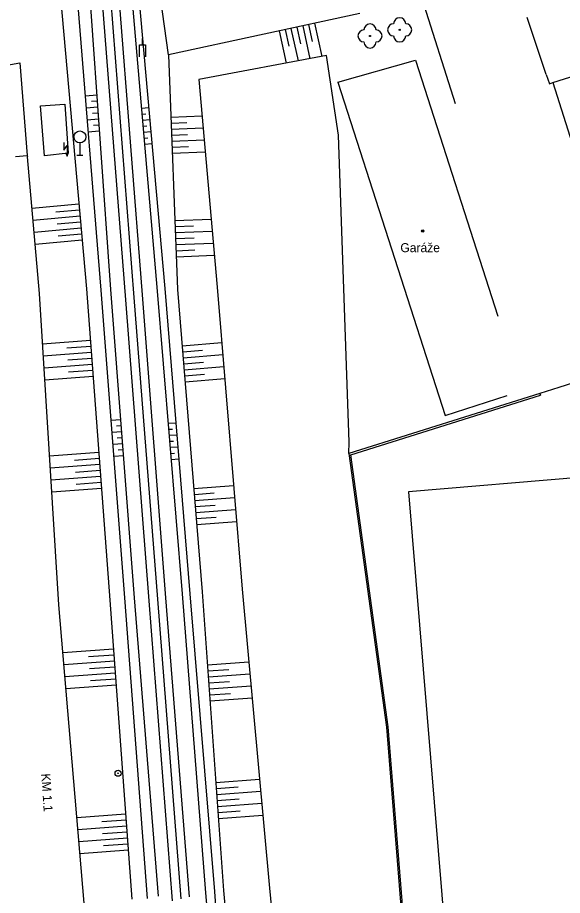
# Model space of a CAD drawing. Extents: x -539244 to -537359, y -1183785 to -1181851.
# Drawn here: x -537718.9 to -537673.7, y -1182189.8 to -1182116.9 of the extents above; entities that cross this region are included whole.
import ezdxf

# ---------------------------------------------------------------- set-up
doc = ezdxf.new("R2010")
doc.units = 0
for name, color, linetype in [('Vrstva 10', 7, 'Continuous'), ('Vrstva 12', 7, 'Continuous'), ('Vrstva 13', 7, 'Continuous'), ('Vrstva 14', 7, 'Continuous'), ('Vrstva 15', 7, 'Continuous'), ('Vrstva 22', 7, 'Continuous'), ('Vrstva 24', 7, 'Continuous'), ('Vrstva 38', 7, 'Continuous'), ('Vrstva 39', 7, 'Continuous'), ('Vrstva 41', 7, 'Continuous'), ('Vrstva 5', 7, 'Continuous'), ('Vrstva 7', 7, 'Continuous'), ('Vrstva 8', 7, 'Continuous')]:
    doc.layers.add(name, color=color, linetype=linetype)

msp = doc.modelspace()

# ---------------------------------------------------------------- linework, layer by layer
at = {"layer": 'Vrstva 10'}
msp.add_line((-537689.19, -1182103.13), (-537682.58, -1182124.019), dxfattribs=at)
at = {"layer": 'Vrstva 12'}
for p, q in [((-537711.952, -1182114.759), (-537709.968, -1182140.329)), ((-537708.55, -1182139.921), (-537710.51, -1182114.75)), ((-537713.75, -1182127.309), (-537713.75, -1182128.309)), ((-537714, -1182128.309), (-537713.5, -1182128.309)), ((-537709.968, -1182140.329), (-537708.028, -1182165.312)), ((-537706.602, -1182165.047), (-537708.55, -1182139.921)), ((-537704.656, -1182189.88), (-537706.602, -1182165.047)), ((-537708.028, -1182165.312), (-537706.086, -1182190.197))]:
    msp.add_line(p, q, dxfattribs=at)
for centre, radius in [((-537713.75, -1182126.809), 0.5), ((-537710.58, -1182179.624), 0.25), ((-537710.58, -1182179.624), 0.03)]:
    msp.add_circle(centre, radius, dxfattribs=at)
at = {"layer": 'Vrstva 13'}
for p, q in [((-537711.23, -1182114.755), (-537709.258, -1182140.125)), ((-537709.258, -1182140.125), (-537707.316, -1182165.18)), ((-537707.316, -1182165.18), (-537705.372, -1182190.039))]:
    msp.add_line(p, q, dxfattribs=at)
at = {"layer": 'Vrstva 14'}
for p, q in [((-537706.396, -1182120.004), (-537707.724, -1182110.357)), ((-537707.33, -1182139.284), (-537709.748, -1182111.262)), ((-537709.198, -1182111.395), (-537706.702, -1182139.384)), ((-537711.174, -1182139.479), (-537713.11, -1182112.226)), ((-537714.084, -1182114.029), (-537712.014, -1182139.53)), ((-537715.384, -1182115.108), (-537713.198, -1182139.404)), ((-537690.5, -1182116.556), (-537706.396, -1182120.004)), ((-537706.396, -1182120.004), (-537705.632, -1182139.457)), ((-537733.226, -1182123.066), (-537718.732, -1182120.669)), ((-537713.198, -1182139.404), (-537711.262, -1182165.246)), ((-537712.014, -1182139.53), (-537710.046, -1182165.064)), ((-537709.2, -1182165.065), (-537711.174, -1182139.479)), ((-537705.238, -1182164.741), (-537707.33, -1182139.284)), ((-537706.702, -1182139.384), (-537704.61, -1182164.735)), ((-537705.632, -1182139.457), (-537703.582, -1182164.572)), ((-537703.582, -1182164.572), (-537701.808, -1182189.341)), ((-537711.262, -1182165.246), (-537709.424, -1182190.062)), ((-537710.046, -1182165.064), (-537708.156, -1182190.022)), ((-537707.232, -1182189.835), (-537709.2, -1182165.065)), ((-537703.274, -1182189.536), (-537705.238, -1182164.741)), ((-537704.61, -1182164.735), (-537702.578, -1182189.421)), ((-537701.808, -1182189.341), (-537699.502, -1182214.94)), ((-537701.302, -1182215.217), (-537703.274, -1182189.536)), ((-537702.578, -1182189.421), (-537700.582, -1182215.071))]:
    msp.add_line(p, q, dxfattribs=at)
msp.add_lwpolyline([(-537718.732, -1182120.669), (-537718.118, -1182128.34), (-537718.108, -1182128.458)], dxfattribs=at)
at = {"layer": 'Vrstva 15'}
for p, q in [((-537696.702, -1182117.901), (-537696.404, -1182119.276)), ((-537696.214, -1182117.795), (-537695.627, -1182120.5)), ((-537695.726, -1182117.689), (-537695.424, -1182119.081)), ((-537695.236, -1182117.583), (-537694.645, -1182120.316)), ((-537694.748, -1182117.477), (-537694.442, -1182118.887)), ((-537694.26, -1182117.371), (-537693.66, -1182120.131)), ((-537697.192, -1182118.007), (-537696.61, -1182120.684)), ((-537712.32, -1182123.341), (-537713.322, -1182123.412)), ((-537712.25, -1182124.338), (-537713.24, -1182124.409)), ((-537712.286, -1182123.839), (-537712.784, -1182123.875)), ((-537708.614, -1182124.416), (-537708.04, -1182124.366)), ((-537712.214, -1182124.837), (-537712.708, -1182124.872)), ((-537708.57, -1182124.914), (-537708.284, -1182124.889)), ((-537706.194, -1182125.152), (-537703.604, -1182125.051)), ((-537712.18, -1182125.336), (-537713.16, -1182125.405)), ((-537712.144, -1182125.834), (-537712.632, -1182125.869)), ((-537708.528, -1182125.412), (-537707.952, -1182125.362)), ((-537708.484, -1182125.91), (-537708.196, -1182125.885)), ((-537706.174, -1182125.652), (-537704.868, -1182125.601)), ((-537712.108, -1182126.333), (-537713.078, -1182126.402)), ((-537708.442, -1182126.408), (-537707.864, -1182126.358)), ((-537706.154, -1182126.152), (-537703.516, -1182126.048)), ((-537706.134, -1182126.651), (-537704.804, -1182126.599)), ((-537708.398, -1182126.906), (-537708.108, -1182126.881)), ((-537708.356, -1182127.405), (-537707.774, -1182127.354)), ((-537706.116, -1182127.151), (-537703.428, -1182127.045)), ((-537706.096, -1182127.65), (-537704.74, -1182127.597)), ((-537706.076, -1182128.15), (-537703.34, -1182128.043)), ((-537713.83, -1182132.384), (-537717.734, -1182132.735)), ((-537713.784, -1182132.882), (-537715.738, -1182133.057)), ((-537713.74, -1182133.38), (-537717.646, -1182133.731)), ((-537713.694, -1182133.878), (-537715.648, -1182134.053)), ((-537705.856, -1182133.749), (-537702.846, -1182133.63)), ((-537713.65, -1182134.376), (-537717.56, -1182134.727)), ((-537705.836, -1182134.248), (-537704.32, -1182134.189)), ((-537705.818, -1182134.748), (-537702.758, -1182134.628)), ((-537713.56, -1182135.372), (-537717.472, -1182135.724)), ((-537713.606, -1182134.874), (-537715.56, -1182135.05)), ((-537705.798, -1182135.247), (-537704.256, -1182135.187)), ((-537705.778, -1182135.747), (-537702.67, -1182135.625)), ((-537705.758, -1182136.247), (-537704.192, -1182136.185)), ((-537705.738, -1182136.746), (-537702.582, -1182136.622)), ((-537712.876, -1182143.698), (-537716.854, -1182143.996)), ((-537705.25, -1182144.144), (-537701.966, -1182143.876)), ((-537712.802, -1182144.695), (-537716.792, -1182144.994)), ((-537712.838, -1182144.197), (-537714.83, -1182144.346)), ((-537705.208, -1182144.642), (-537703.566, -1182144.508)), ((-537705.168, -1182145.141), (-537701.882, -1182144.872)), ((-537712.764, -1182145.194), (-537714.762, -1182145.344)), ((-537705.128, -1182145.639), (-537703.484, -1182145.505)), ((-537712.726, -1182145.693), (-537716.73, -1182145.992)), ((-537712.688, -1182146.191), (-537714.694, -1182146.341)), ((-537705.086, -1182146.137), (-537701.798, -1182145.869)), ((-537712.652, -1182146.69), (-537716.668, -1182146.991)), ((-537705.046, -1182146.636), (-537703.402, -1182146.502)), ((-537705.006, -1182147.134), (-537701.716, -1182146.866)), ((-537710.34, -1182150.283), (-537711.18, -1182150.348)), ((-537706.402, -1182150.575), (-537705.782, -1182150.524)), ((-537710.264, -1182151.28), (-537711.104, -1182151.345)), ((-537710.302, -1182150.782), (-537710.722, -1182150.814)), ((-537706.362, -1182151.073), (-537706.052, -1182151.048)), ((-537710.224, -1182151.779), (-537710.644, -1182151.811)), ((-537706.32, -1182151.572), (-537705.7, -1182151.521)), ((-537706.28, -1182152.07), (-537705.97, -1182152.045)), ((-537710.186, -1182152.277), (-537711.026, -1182152.342)), ((-537710.148, -1182152.776), (-537710.568, -1182152.808)), ((-537706.238, -1182152.568), (-537705.618, -1182152.517)), ((-537712.178, -1182152.999), (-537716.274, -1182153.306)), ((-537712.142, -1182153.498), (-537714.192, -1182153.652)), ((-537710.11, -1182153.274), (-537710.95, -1182153.339)), ((-537706.198, -1182153.067), (-537705.888, -1182153.041)), ((-537706.156, -1182153.565), (-537705.536, -1182153.514)), ((-537712.104, -1182153.996), (-537716.212, -1182154.304)), ((-537712.03, -1182154.994), (-537716.15, -1182155.302)), ((-537712.066, -1182154.495), (-537714.124, -1182154.649)), ((-537711.992, -1182155.492), (-537714.056, -1182155.647)), ((-537704.282, -1182155.996), (-537700.978, -1182155.726)), ((-537711.954, -1182155.991), (-537716.088, -1182156.301)), ((-537704.242, -1182156.494), (-537702.588, -1182156.359)), ((-537704.2, -1182156.992), (-537700.894, -1182156.722)), ((-537704.16, -1182157.491), (-537702.506, -1182157.356)), ((-537704.12, -1182157.989), (-537700.812, -1182157.719)), ((-537704.078, -1182158.487), (-537702.424, -1182158.352)), ((-537704.038, -1182158.986), (-537700.728, -1182158.716)), ((-537710.96, -1182169.315), (-537715.17, -1182169.627)), ((-537710.886, -1182170.313), (-537715.086, -1182170.624)), ((-537710.924, -1182169.814), (-537713.026, -1182169.97)), ((-537703.148, -1182170.63), (-537699.71, -1182170.383)), ((-537710.85, -1182170.811), (-537712.946, -1182170.967)), ((-537703.112, -1182171.128), (-537701.388, -1182171.005)), ((-537710.812, -1182171.31), (-537715, -1182171.62)), ((-537710.776, -1182171.809), (-537712.868, -1182171.963)), ((-537703.076, -1182171.627), (-537699.62, -1182171.379)), ((-537710.738, -1182172.307), (-537714.916, -1182172.616)), ((-537703.04, -1182172.126), (-537701.308, -1182172.002)), ((-537703.004, -1182172.624), (-537699.53, -1182172.376)), ((-537702.97, -1182173.123), (-537701.226, -1182172.998)), ((-537702.934, -1182173.622), (-537699.44, -1182173.372)), ((-537702.45, -1182180.376), (-537698.828, -1182180.117)), ((-537702.414, -1182180.875), (-537700.598, -1182180.745)), ((-537702.378, -1182181.374), (-537698.736, -1182181.113)), ((-537702.342, -1182181.872), (-537700.518, -1182181.742)), ((-537702.306, -1182182.371), (-537698.646, -1182182.109)), ((-537702.27, -1182182.87), (-537700.436, -1182182.738)), ((-537709.948, -1182183.006), (-537714.01, -1182183.307)), ((-537709.91, -1182183.505), (-537711.938, -1182183.655)), ((-537702.236, -1182183.369), (-537698.556, -1182183.105)), ((-537709.874, -1182184.003), (-537713.924, -1182184.303)), ((-537709.836, -1182184.502), (-537711.86, -1182184.652)), ((-537709.8, -1182185.001), (-537713.84, -1182185.3)), ((-537709.762, -1182185.499), (-537711.78, -1182185.649)), ((-537709.726, -1182185.998), (-537713.756, -1182186.296))]:
    msp.add_line(p, q, dxfattribs=at)
at = {"layer": 'Vrstva 22'}
for centre in [(-537687.184, -1182117.915), (-537689.648, -1182118.426)]:
    msp.add_circle(centre, 0.05, dxfattribs=at)
for centre, start, end in [((-537687.184, -1182117.415), 0, 180), ((-537690.148, -1182118.426), 90, 270), ((-537689.648, -1182117.926), 0, 180), ((-537689.148, -1182118.426), 270, 90), ((-537687.684, -1182117.915), 90, 270), ((-537686.684, -1182117.915), 270, 90), ((-537687.184, -1182118.415), 180, 0), ((-537689.648, -1182118.926), 180, 0)]:
    msp.add_arc(centre, 0.5, start, end, dxfattribs=at)
at = {"layer": 'Vrstva 24'}
for p, q in [((-537715.07, -1182127.274), (-537715.07, -1182127.9)), ((-537715.07, -1182127.9), (-537714.82, -1182127.525)), ((-537714.82, -1182127.525), (-537714.82, -1182128.4)), ((-537714.93, -1182128.155), (-537714.82, -1182128.4)), ((-537714.82, -1182128.4), (-537714.71, -1182128.155))]:
    msp.add_line(p, q, dxfattribs=at)
at = {"layer": 'Vrstva 38'}
msp.add_line((-537708.558, -1182119.163), (-537708.558, -1182118.633), dxfattribs=at)
msp.add_lwpolyline([(-537708.808, -1182120.163), (-537708.808, -1182119.163), (-537708.308, -1182119.163), (-537708.308, -1182120.163)], dxfattribs=at)
at = {"layer": 'Vrstva 39'}
for radius in [0.09, 0.0398]:
    msp.add_circle((-537685.27, -1182134.61), radius, dxfattribs=at)
at = {"layer": 'Vrstva 5'}
for p, q in [((-537675.008, -1182121.623), (-537676.59, -1182116.88)), ((-537692.32, -1182122.27), (-537685.87, -1182120.44)), ((-537685.87, -1182120.44), (-537679.024, -1182141.684)), ((-537692.32, -1182122.27), (-537683.41, -1182149.92)), ((-537675.008, -1182121.623), (-537674.74, -1182122.39)), ((-537674.451, -1182122.299), (-537672.69, -1182127.89)), ((-537717.01, -1182124.23), (-537715.01, -1182124.09)), ((-537716.68, -1182128.38), (-537717.01, -1182124.23)), ((-537715.01, -1182124.09), (-537714.71, -1182128.15)), ((-537714.71, -1182128.15), (-537716.68, -1182128.38)), ((-537683.41, -1182149.92), (-537678.241, -1182148.254)), ((-537671.3, -1182155), (-537686.46, -1182156.25))]:
    msp.add_line(p, q, dxfattribs=at)
for points in [[(-537674.74, -1182122.39), (-537674.451, -1182122.299), (-537615.522, -1182103.739)], [(-537686.46, -1182156.25), (-537681.864, -1182211.801), (-537681.741, -1182213.289), (-537679.69, -1182238.08)]]:
    msp.add_lwpolyline(points, dxfattribs=at)
at = {"layer": 'Vrstva 7'}
for p, q in [((-537693.251, -1182120.054), (-537703.87, -1182122.045)), ((-537703.87, -1182122.045), (-537702.35, -1182139.267)), ((-537719.089, -1182128.437), (-537718.118, -1182128.34)), ((-537717.114, -1182139.797), (-537718.108, -1182128.458)), ((-537715.508, -1182165.644), (-537717.114, -1182139.797)), ((-537702.35, -1182139.267), (-537700.26, -1182164.335)), ((-537675.54, -1182148.09), (-537691.412, -1182153.093)), ((-537691.246, -1182153.198), (-537675.494, -1182148.233)), ((-537675.54, -1182148.09), (-537675.494, -1182148.233)), ((-537700.26, -1182164.335), (-537698.006, -1182189.162)), ((-537713.406, -1182190.413), (-537715.508, -1182165.644)), ((-537698.006, -1182189.162), (-537695.458, -1182214.27))]:
    msp.add_line(p, q, dxfattribs=at)
for points in [[(-537691.412, -1182153.093), (-537691.39, -1182152.15), (-537692.27, -1182126.65), (-537693.251, -1182120.054)], [(-537691.412, -1182153.093), (-537688.289, -1182175.796), (-537683.81, -1182231.471), (-537683.419, -1182237.757), (-537681.909, -1182246.799), (-537681.682, -1182249.467), (-537682.04, -1182249.507), (-537681.519, -1182256.983), (-537681.099, -1182261.237), (-537680.831, -1182263.234), (-537680.99, -1182265.39), (-537680.816, -1182267.732), (-537644.5, -1182258.035), (-537639.249, -1182256.524), (-537620.413, -1182251.368), (-537618.296, -1182251.169), (-537599.133, -1182249.42), (-537578.459, -1182249.459)], [(-537578.45, -1182249.31), (-537599.14, -1182249.27), (-537618.31, -1182251.02), (-537620.44, -1182251.22), (-537639.29, -1182256.38), (-537644.54, -1182257.89), (-537647.532, -1182258.689), (-537680.68, -1182267.54), (-537680.84, -1182265.39), (-537680.68, -1182263.23), (-537680.95, -1182261.22), (-537681.37, -1182256.97), (-537681.88, -1182249.64), (-537681.52, -1182249.6), (-537681.76, -1182246.78), (-537683.27, -1182237.74), (-537683.66, -1182231.46), (-537688.14, -1182175.78), (-537691.246, -1182153.198)]]:
    msp.add_lwpolyline(points, dxfattribs=at)
at = {"layer": 'Vrstva 8'}
for p, q in [((-537668.87, -1182145.96), (-537673.97, -1182147.6)), ((-537673.97, -1182147.6), (-537675.54, -1182148.09))]:
    msp.add_line(p, q, dxfattribs=at)

# ---------------------------------------------------------------- texts
at = {"layer": 'Vrstva 41'}
msp.add_text('Garáže', height=0.75, dxfattribs=at).set_placement((-537687.127, -1182136.373))
msp.add_text('KM 1.1', height=0.75, rotation=273.6, dxfattribs=at).set_placement((-537716.952, -1182179.662))

doc.saveas('drawing.dxf')
